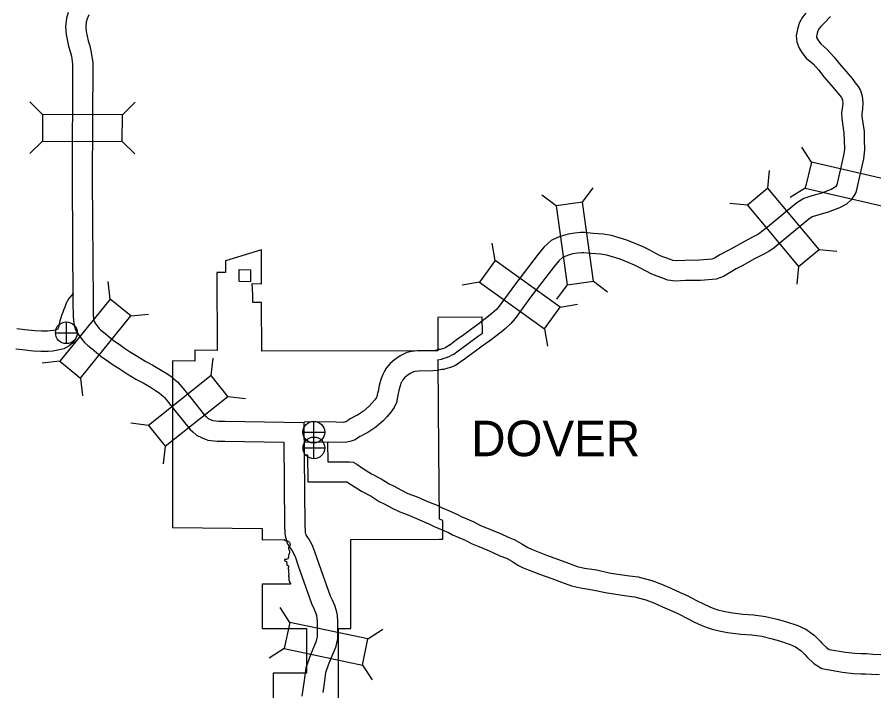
# Model space of a CAD drawing. Extents: x 1374139 to 1377472, y 1168351 to 1170484.
# Drawn here: x 1374519.6 to 1374646.9, y 1170238.9 to 1170339 of the extents above; entities that cross this region are included whole.
import ezdxf

# ---------------------------------------------------------------- set-up
doc = ezdxf.new("R2010")
doc.units = 0
doc.layers.add('Default', color=7, linetype='Continuous')

msp = doc.modelspace()

# ---------------------------------------------------------------- linework, layer by layer
at = {"layer": 'Default'}
for p, q in [((1374523.36, 1170324.58), (1374521.5, 1170326.45)), ((1374535.24, 1170324.53), (1374537.12, 1170326.4)), ((1374523.35, 1170320.62), (1374521.48, 1170318.76)), ((1374535.23, 1170320.57), (1374537.09, 1170318.7)), ((1374637.65, 1170317.48), (1374636.25, 1170319.72)), ((1374631.18, 1170313.62), (1374631.42, 1170316.25)), ((1374603.62, 1170311.55), (1374605.21, 1170313.66)), ((1374636.75, 1170313.62), (1374634.5, 1170312.23)), ((1374599.7, 1170311), (1374597.59, 1170312.59)), ((1374628.14, 1170311.08), (1374625.51, 1170311.32)), ((1374590.63, 1170302.85), (1374590.19, 1170305.45)), ((1374638.79, 1170304.5), (1374641.42, 1170304.26)), ((1374635.75, 1170301.96), (1374635.51, 1170299.33)), ((1374533.42, 1170297.12), (1374533.15, 1170299.74)), ((1374588.33, 1170299.63), (1374585.73, 1170299.19)), ((1374601.35, 1170299.24), (1374599.76, 1170297.13)), ((1374605.27, 1170299.79), (1374607.37, 1170298.2)), ((1374600.3, 1170295.95), (1374602.91, 1170296.39)), ((1374536.5, 1170294.62), (1374539.12, 1170294.9)), ((1374526.91, 1170290.5), (1374526.91, 1170293.75)), ((1374598, 1170292.73), (1374598.44, 1170290.13)), ((1374525.28, 1170292.13), (1374528.53, 1170292.13)), ((1374525.94, 1170287.89), (1374523.31, 1170287.62)), ((1374548.45, 1170285.75), (1374548.75, 1170288.37)), ((1374529.01, 1170285.4), (1374529.29, 1170282.77)), ((1374550.91, 1170282.65), (1374553.53, 1170282.35)), ((1374539.14, 1170278.36), (1374536.52, 1170278.67)), ((1374563.69, 1170275.72), (1374563.69, 1170278.97)), ((1374562.07, 1170277.35), (1374565.32, 1170277.35)), ((1374563.71, 1170273.39), (1374563.71, 1170276.64)), ((1374541.6, 1170275.26), (1374541.3, 1170272.64)), ((1374562.09, 1170275.01), (1374565.34, 1170275.01)), ((1374560.12, 1170249.07), (1374558.67, 1170251.29)), ((1374571.74, 1170246.62), (1374573.95, 1170248.06)), ((1374559.3, 1170245.2), (1374557.08, 1170243.76)), ((1374570.92, 1170242.74), (1374572.36, 1170240.53))]:
    msp.add_line(p, q, dxfattribs=at)
for points in [[(1374527.17, 1170339.73), (1374526.92, 1170338.89), (1374526.77, 1170337.57), (1374526.89, 1170336.43), (1374527.24, 1170334.73), (1374527.5, 1170333.94), (1374527.67, 1170333.24), (1374527.83, 1170332.06), (1374527.77, 1170314.82), (1374527.88, 1170296.68), (1374527.91, 1170294.6), (1374527.96, 1170293.93), (1374528.08, 1170293.27), (1374528.29, 1170292.57), (1374528.76, 1170291.78), (1374529.06, 1170291.35), (1374529.59, 1170290.69), (1374530.11, 1170290.23), (1374530.73, 1170289.73), (1374531.38, 1170289.19), (1374532.08, 1170288.61), (1374533.19, 1170287.84), (1374533.87, 1170287.34), (1374534.74, 1170286.8), (1374535.97, 1170286.04), (1374537.24, 1170285.25), (1374538.31, 1170284.69), (1374539.43, 1170284.02), (1374540.18, 1170283.56), (1374540.69, 1170283.2), (1374541.05, 1170282.92), (1374541.35, 1170282.66), (1374541.51, 1170282.49), (1374543.06, 1170280.56)], [(1374530.24, 1170339.39), (1374530.02, 1170338.79), (1374529.87, 1170338.29), (1374529.79, 1170337.55), (1374529.85, 1170336.89), (1374530.15, 1170335.51), (1374530.39, 1170334.76), (1374530.62, 1170333.79), (1374530.83, 1170332.26), (1374530.77, 1170314.83), (1374530.88, 1170296.71), (1374530.91, 1170294.74), (1374530.94, 1170294.31), (1374531, 1170293.97), (1374531.05, 1170293.79), (1374531.28, 1170293.41), (1374531.47, 1170293.15), (1374531.77, 1170292.76), (1374532.06, 1170292.51), (1374532.63, 1170292.05), (1374533.28, 1170291.51), (1374533.89, 1170291.01), (1374534.94, 1170290.28), (1374535.55, 1170289.82), (1374536.32, 1170289.35), (1374537.54, 1170288.59), (1374538.73, 1170287.86), (1374539.77, 1170287.31), (1374540.99, 1170286.59), (1374541.84, 1170286.06), (1374542.48, 1170285.61), (1374542.96, 1170285.24), (1374543.44, 1170284.82), (1374543.78, 1170284.45), (1374545.4, 1170282.45)], [(1374636.82, 1170339.63), (1374636.32, 1170339.02), (1374635.87, 1170338.21), (1374635.62, 1170337.43), (1374635.37, 1170336.28), (1374635.5, 1170335.3), (1374635.83, 1170334.42), (1374636.24, 1170333.76), (1374636.88, 1170332.95), (1374637.9, 1170332.09), (1374638.7, 1170331.19), (1374639.5, 1170330.18), (1374640.53, 1170328.98), (1374641.4, 1170327.98), (1374641.82, 1170327.43), (1374642.12, 1170327.07), (1374642.18, 1170326.95), (1374642.27, 1170326.67), (1374642.31, 1170326.3), (1374642.26, 1170325.69), (1374642.14, 1170324.86), (1374642.16, 1170323.97), (1374642.35, 1170322.88), (1374642.48, 1170321.8), (1374642.51, 1170320.75), (1374642.56, 1170319.42), (1374642.44, 1170318.49), (1374641.42, 1170314.11), (1374641.24, 1170313.82), (1374641.11, 1170313.69), (1374640.61, 1170313.42), (1374639.18, 1170312.89), (1374637.74, 1170312.45), (1374636.52, 1170312.1), (1374635.51, 1170311.45), (1374631.14, 1170307.81), (1374630.31, 1170307.15), (1374629.78, 1170306.78), (1374628.88, 1170306.31), (1374627.7, 1170305.68), (1374626.03, 1170304.76), (1374625.06, 1170304.25), (1374624.04, 1170303.69), (1374623.27, 1170303.21), (1374622.87, 1170303.07), (1374621, 1170302.9), (1374618.85, 1170302.86), (1374617.6, 1170302.81), (1374617.06, 1170302.88), (1374616.69, 1170303.02), (1374615.17, 1170303.57), (1374613.53, 1170304.43), (1374612.63, 1170304.9), (1374611.55, 1170305.36), (1374610.22, 1170305.88), (1374607.92, 1170306.57), (1374606.7, 1170306.78), (1374605.21, 1170306.89), (1374603.99, 1170307.02), (1374603.32, 1170307.02), (1374602.48, 1170306.91), (1374601.52, 1170306.78), (1374600.8, 1170306.56), (1374599.92, 1170306.28), (1374598.98, 1170305.84), (1374597.92, 1170304.9), (1374597.04, 1170303.81), (1374593.5, 1170299.22), (1374591.25, 1170296.08), (1374590.84, 1170295.58), (1374590.15, 1170294.98), (1374589.63, 1170294.52), (1374588.07, 1170293.35), (1374586.96, 1170292.54), (1374585.99, 1170291.84), (1374585.03, 1170291.16), (1374584.43, 1170290.68), (1374583.9, 1170290.3)], [(1374640.5, 1170339.14), (1374639.62, 1170338.2), (1374639.05, 1170337.62), (1374638.82, 1170337.33), (1374638.63, 1170337), (1374638.52, 1170336.65), (1374638.42, 1170336.16), (1374638.43, 1170336.02), (1374638.54, 1170335.74), (1374638.7, 1170335.49), (1374639.05, 1170335.04), (1374640, 1170334.24), (1374640.99, 1170333.13), (1374641.82, 1170332.09), (1374642.81, 1170330.93), (1374643.71, 1170329.89), (1374644.18, 1170329.29), (1374644.63, 1170328.73), (1374644.96, 1170328.12), (1374645.21, 1170327.29), (1374645.32, 1170326.36), (1374645.24, 1170325.35), (1374645.14, 1170324.67), (1374645.15, 1170324.26), (1374645.31, 1170323.33), (1374645.48, 1170322.03), (1374645.51, 1170320.84), (1374645.56, 1170319.29), (1374645.4, 1170317.96), (1374644.24, 1170312.98), (1374643.6, 1170311.91), (1374642.86, 1170311.23), (1374641.84, 1170310.68), (1374640.14, 1170310.05), (1374638.59, 1170309.58), (1374637.78, 1170309.34), (1374637.29, 1170309.03), (1374633.03, 1170305.48), (1374632.1, 1170304.74), (1374631.35, 1170304.22), (1374630.28, 1170303.65), (1374629.12, 1170303.04), (1374627.45, 1170302.12), (1374626.49, 1170301.62), (1374625.56, 1170301.1), (1374624.58, 1170300.49), (1374623.51, 1170300.11), (1374621.16, 1170299.91), (1374618.94, 1170299.87), (1374617.47, 1170299.8), (1374616.32, 1170299.95), (1374615.65, 1170300.2), (1374613.96, 1170300.81), (1374612.15, 1170301.77), (1374611.35, 1170302.18), (1374610.41, 1170302.58), (1374609.24, 1170303.04), (1374607.24, 1170303.64), (1374606.34, 1170303.79), (1374604.93, 1170303.9), (1374603.83, 1170304.02), (1374603.53, 1170304.02), (1374602.87, 1170303.94), (1374602.15, 1170303.83), (1374601.68, 1170303.7), (1374601.02, 1170303.48), (1374600.65, 1170303.31), (1374600.1, 1170302.82), (1374599.4, 1170301.95), (1374595.91, 1170297.43), (1374593.63, 1170294.24), (1374592.99, 1170293.48), (1374592.13, 1170292.73), (1374591.52, 1170292.19), (1374589.86, 1170290.94), (1374588.73, 1170290.11), (1374587.73, 1170289.39), (1374586.83, 1170288.76), (1374586.23, 1170288.28), (1374585.62, 1170287.85)], [(1374582.13, 1170289.46), (1374555.96, 1170289.37), (1374555.93, 1170296.62), (1374554.62, 1170296.64), (1374554.61, 1170297.71), (1374554.55, 1170299.44), (1374555.92, 1170299.42), (1374555.91, 1170300.99), (1374555.9, 1170304.45), (1374550.56, 1170302.81), (1374550.56, 1170301.06), (1374549.28, 1170301.08), (1374549.33, 1170289.49), (1374546.01, 1170289.55), (1374546.02, 1170287.9), (1374542.7, 1170287.96), (1374542.71, 1170274.75), (1374542.71, 1170263.19), (1374556, 1170263.02), (1374556, 1170261.37), (1374559.29, 1170261.38), (1374559.49, 1170261.26), (1374559.75, 1170261.21), (1374559.94, 1170261.1), (1374560.07, 1170260.93), (1374560.16, 1170260.76), (1374560.16, 1170260.57), (1374560.11, 1170260.46), (1374559.99, 1170260.33), (1374559.93, 1170260.23), (1374559.93, 1170260.03), (1374559.97, 1170259.9), (1374560.04, 1170259.8), (1374560.06, 1170259.65), (1374560.07, 1170259.44)], [(1374552.61, 1170301.52), (1374554.26, 1170301.5), (1374554.27, 1170299.69), (1374552.62, 1170299.72), (1374552.61, 1170301.52)], [(1374527.91, 1170297.99), (1374527.9, 1170297.98), (1374527.3, 1170297.21), (1374526.89, 1170296.51), (1374526.7, 1170295.95), (1374526.5, 1170295.46), (1374526.34, 1170295.04), (1374526.26, 1170294.83), (1374526.09, 1170294.36), (1374525.96, 1170293.89), (1374525.81, 1170293.19), (1374525.75, 1170292.92), (1374525.64, 1170292.69), (1374525.63, 1170292.66), (1374525.62, 1170292.66), (1374525.42, 1170292.55), (1374525.07, 1170292.46), (1374524.57, 1170292.39), (1374524.1, 1170292.35), (1374523.21, 1170292.35), (1374522.23, 1170292.4), (1374520.72, 1170292.58), (1374519.54, 1170292.7)], [(1374582.16, 1170287.81), (1374582.15, 1170288.1), (1374582.65, 1170288.22), (1374583.06, 1170288.33), (1374583.43, 1170288.45), (1374583.79, 1170288.61), (1374584.18, 1170288.8), (1374584.49, 1170288.96), (1374584.72, 1170289.11), (1374584.94, 1170289.27), (1374586.46, 1170290.4), (1374588.18, 1170291.67), (1374588.75, 1170292.08), (1374588.74, 1170294.46), (1374582.13, 1170294.4), (1374582.13, 1170289.46)], [(1374528.59, 1170291.94), (1374528.27, 1170291.2), (1374527.85, 1170290.61), (1374527.31, 1170290.17), (1374526.53, 1170289.73), (1374525.66, 1170289.52), (1374524.92, 1170289.41), (1374524.22, 1170289.34), (1374523.12, 1170289.35), (1374521.98, 1170289.41), (1374520.39, 1170289.59), (1374519.4, 1170289.7)], [(1374583.91, 1170290.32), (1374583.56, 1170290.08), (1374583.31, 1170289.91), (1374583.16, 1170289.84), (1374582.82, 1170289.75), (1374582.46, 1170289.65), (1374582.21, 1170289.63), (1374581.59, 1170289.46), (1374581.36, 1170289.45), (1374579.1, 1170289.42), (1374578.24, 1170289.32), (1374577.54, 1170289.17), (1374576.52, 1170288.71), (1374575.68, 1170288.11), (1374575.04, 1170287.55), (1374574.46, 1170286.86), (1374574.14, 1170286.3), (1374573.95, 1170285.94), (1374573.67, 1170285.18), (1374573.4, 1170284.27), (1374573.24, 1170283.44), (1374573.12, 1170282.89), (1374573.08, 1170282.67), (1374573.01, 1170282.51), (1374572.77, 1170282.17), (1374572.32, 1170281.64), (1374571.92, 1170281.22), (1374571.08, 1170280.48), (1374570.18, 1170279.9), (1374569.84, 1170279.72), (1374569.18, 1170279.38), (1374568.82, 1170279.15), (1374568.64, 1170279.01), (1374568.49, 1170278.91), (1374568.39, 1170278.87), (1374568.12, 1170278.81), (1374565.92, 1170278.87), (1374562.24, 1170278.83)], [(1374585.6, 1170287.84), (1374585.24, 1170287.59), (1374584.76, 1170287.27), (1374584.17, 1170287.01), (1374583.61, 1170286.86), (1374582.99, 1170286.68), (1374582.73, 1170286.66), (1374582.09, 1170286.5), (1374581.5, 1170286.45), (1374579.28, 1170286.42), (1374578.73, 1170286.36), (1374578.49, 1170286.31), (1374578.02, 1170286.09), (1374577.53, 1170285.74), (1374577.18, 1170285.45), (1374576.93, 1170285.14), (1374576.76, 1170284.84), (1374576.7, 1170284.72), (1374576.52, 1170284.24), (1374576.32, 1170283.56), (1374576.18, 1170282.83), (1374576.07, 1170282.31), (1374575.97, 1170281.77), (1374575.63, 1170281.03), (1374575.15, 1170280.34), (1374574.56, 1170279.64), (1374574.01, 1170279.06), (1374572.89, 1170278.08), (1374571.7, 1170277.32), (1374571.24, 1170277.07), (1374570.69, 1170276.78), (1374570.55, 1170276.69), (1374570.36, 1170276.55), (1374569.85, 1170276.22), (1374569.26, 1170275.99), (1374568.41, 1170275.8), (1374565.89, 1170275.87), (1374562.27, 1170275.83)], [(1374567.36, 1170234.97), (1374567.36, 1170248.18), (1374569.19, 1170248.18), (1374569.19, 1170254.79), (1374569.19, 1170261.4), (1374582.39, 1170261.44), (1374582.89, 1170261.44), (1374582.86, 1170264.21), (1374582.36, 1170264.44), (1374582.27, 1170274.62), (1374582.16, 1170287.81)], [(1374545.41, 1170282.44), (1374547.44, 1170279.88), (1374547.71, 1170279.67), (1374547.99, 1170279.4), (1374548.31, 1170279.25), (1374548.68, 1170279.1), (1374549.51, 1170279), (1374550.52, 1170278.99), (1374562.22, 1170278.8), (1374562.35, 1170263.53), (1374562.39, 1170262.61), (1374562.42, 1170262.38), (1374562.44, 1170262.31), (1374562.5, 1170262.08), (1374562.65, 1170261.83), (1374563.01, 1170261.33), (1374563.39, 1170260.68), (1374563.76, 1170259.76), (1374564.19, 1170258.48), (1374566.14, 1170253.01), (1374566.4, 1170252.42), (1374566.77, 1170251.65), (1374567.02, 1170250.83), (1374567.14, 1170250.1), (1374567.21, 1170249.27), (1374567.21, 1170247.92), (1374567.21, 1170246.66), (1374566.94, 1170245.36), (1374565.99, 1170243.14), (1374565.44, 1170241.61), (1374565.23, 1170240.04), (1374565.01, 1170238.66)], [(1374543.06, 1170280.57), (1374545.3, 1170277.74), (1374545.73, 1170277.4), (1374546.26, 1170276.9), (1374547.1, 1170276.5), (1374547.95, 1170276.16), (1374549.32, 1170276.01), (1374550.47, 1170275.99), (1374559.25, 1170275.85), (1374559.35, 1170263.47), (1374559.39, 1170262.35), (1374559.49, 1170261.68), (1374559.57, 1170261.45), (1374559.73, 1170260.81), (1374559.89, 1170260.6), (1374560.13, 1170260.19), (1374560.49, 1170259.7), (1374560.69, 1170259.35), (1374560.95, 1170258.72), (1374561.36, 1170257.5), (1374563.35, 1170251.89), (1374563.68, 1170251.17), (1374563.96, 1170250.56), (1374564.1, 1170250.13), (1374564.16, 1170249.73), (1374564.21, 1170249.15), (1374564.21, 1170247.92), (1374564.21, 1170246.97), (1374564.06, 1170246.27), (1374563.2, 1170244.24), (1374562.5, 1170242.32), (1374562.26, 1170240.47), (1374562.04, 1170239.1), (1374561.9, 1170238.12)], [(1374565.73, 1170275.83), (1374565.77, 1170272.96), (1374568.45, 1170272.96), (1374569, 1170272.94), (1374569.55, 1170272.87), (1374570.07, 1170272.59), (1374570.93, 1170272.01), (1374572.27, 1170271.17), (1374573.69, 1170270.44), (1374574.9, 1170269.69), (1374575.64, 1170269.31), (1374576.61, 1170268.79), (1374577.67, 1170268.26), (1374578.38, 1170268), (1374579.08, 1170267.74), (1374580.15, 1170267.26), (1374581.23, 1170266.8), (1374582.02, 1170266.48), (1374582.79, 1170266.09), (1374583.97, 1170265.62), (1374585.06, 1170265.12), (1374585.62, 1170264.8), (1374586.42, 1170264.47), (1374587.48, 1170264.01), (1374588.49, 1170263.49), (1374589.35, 1170263.13), (1374590.53, 1170262.65), (1374591.45, 1170262.28), (1374592.56, 1170261.73), (1374593.59, 1170261.33), (1374594.63, 1170260.76), (1374595.5, 1170260.23), (1374596.06, 1170259.95), (1374598.29, 1170259.06), (1374600.08, 1170258.44), (1374601.55, 1170257.87), (1374602.83, 1170257.41), (1374603.92, 1170257.16), (1374605.69, 1170256.88), (1374607.83, 1170256.4), (1374610.6, 1170256.01), (1374611.92, 1170255.86), (1374613.96, 1170255.29), (1374615.38, 1170254.74), (1374616.74, 1170254.15), (1374618.13, 1170253.52), (1374619.19, 1170253.06), (1374620.57, 1170252.34), (1374621.6, 1170251.84), (1374622.57, 1170251.38), (1374623.17, 1170251.13), (1374623.74, 1170250.95), (1374624.58, 1170250.74), (1374625.63, 1170250.54), (1374627.46, 1170250.32), (1374629.07, 1170250.2), (1374630.85, 1170249.98), (1374632.58, 1170249.55), (1374633.8, 1170249.23), (1374635.63, 1170248.61), (1374636.83, 1170248.05), (1374638.06, 1170247.17), (1374638.95, 1170246.31), (1374639.19, 1170246.01), (1374639.88, 1170245.34), (1374640.31, 1170245.07), (1374642.7, 1170244.65), (1374644.12, 1170244.5), (1374645.09, 1170244.46), (1374645.84, 1170244.45), (1374646.79, 1170244.37), (1374647.97, 1170244.32)], [(1374562.33, 1170273.96), (1374562.75, 1170273.96), (1374562.8, 1170269.95), (1374568.39, 1170269.96), (1374568.61, 1170269.95), (1374569.3, 1170269.5), (1374570.79, 1170268.56), (1374572.21, 1170267.83), (1374573.43, 1170267.07), (1374574.26, 1170266.65), (1374575.23, 1170266.13), (1374576.48, 1170265.5), (1374577.34, 1170265.19), (1374577.93, 1170264.96), (1374578.95, 1170264.5), (1374580.08, 1170264.03), (1374580.77, 1170263.75), (1374581.56, 1170263.35), (1374582.79, 1170262.86), (1374583.7, 1170262.44), (1374584.3, 1170262.1), (1374585.23, 1170261.71), (1374586.19, 1170261.29), (1374587.23, 1170260.76), (1374588.21, 1170260.36), (1374589.4, 1170259.87), (1374590.22, 1170259.54), (1374591.35, 1170258.99), (1374592.32, 1170258.61), (1374593.13, 1170258.17), (1374594.03, 1170257.61), (1374594.83, 1170257.21), (1374597.24, 1170256.25), (1374599.05, 1170255.62), (1374600.51, 1170255.06), (1374601.98, 1170254.53), (1374603.34, 1170254.21), (1374605.13, 1170253.93), (1374607.29, 1170253.45), (1374610.22, 1170253.03), (1374611.34, 1170252.9), (1374613.02, 1170252.44), (1374614.23, 1170251.97), (1374615.52, 1170251.41), (1374616.91, 1170250.78), (1374617.9, 1170250.35), (1374619.22, 1170249.66), (1374620.3, 1170249.13), (1374621.36, 1170248.63), (1374622.15, 1170248.31), (1374622.92, 1170248.06), (1374623.95, 1170247.81), (1374625.18, 1170247.58), (1374627.17, 1170247.33), (1374628.78, 1170247.22), (1374630.3, 1170247.03), (1374631.84, 1170246.64), (1374632.93, 1170246.36), (1374634.51, 1170245.82), (1374635.31, 1170245.45), (1374636.13, 1170244.86), (1374636.73, 1170244.28), (1374636.97, 1170243.98), (1374638.03, 1170242.96), (1374639.21, 1170242.22), (1374642.28, 1170241.67), (1374643.9, 1170241.51), (1374645, 1170241.46), (1374645.69, 1170241.45), (1374646.61, 1170241.38), (1374647.78, 1170241.33)], [(1374560.07, 1170259.44), (1374559.99, 1170259.17), (1374559.94, 1170258.98), (1374559.92, 1170258.76), (1374559.89, 1170258.63), (1374559.81, 1170258.54), (1374559.68, 1170258.48), (1374559.56, 1170258.45), (1374559.45, 1170258.45), (1374559.36, 1170258.41), (1374559.35, 1170258.33), (1374559.38, 1170258.25), (1374559.49, 1170258.19), (1374559.61, 1170258.11), (1374559.67, 1170257.95), (1374559.65, 1170257.89), (1374559.67, 1170257.72), (1374559.7, 1170257.59), (1374559.77, 1170257.58), (1374559.84, 1170257.52), (1374559.92, 1170257.4), (1374559.93, 1170257.29), (1374559.88, 1170257.16), (1374559.89, 1170257.04), (1374559.94, 1170256.9), (1374559.95, 1170256.8), (1374559.94, 1170256.66), (1374559.95, 1170256.52), (1374559.99, 1170256.32), (1374559.99, 1170256.18), (1374559.95, 1170256.04), (1374559.95, 1170255.94), (1374559.98, 1170255.82), (1374559.99, 1170255.73), (1374559.99, 1170255.63), (1374559.98, 1170255.55), (1374559.99, 1170255.41), (1374560.02, 1170255.27), (1374560.06, 1170255.13), (1374560.09, 1170255.07), (1374560.14, 1170254.99), (1374560.21, 1170254.85), (1374560.21, 1170254.77)], [(1374560.21, 1170254.77), (1374556.02, 1170254.76), (1374556.04, 1170248.15), (1374562.62, 1170248.16), (1374562.63, 1170241.55), (1374557.63, 1170241.54), (1374557.64, 1170234.93), (1374555.97, 1170234.92), (1374555.9, 1170222.81), (1374558.5, 1170222.8), (1374558.5, 1170216.2), (1374555.9, 1170216.21), (1374549.37, 1170216.28), (1374549.35, 1170209.63), (1374549.39, 1170196.4), (1374542.79, 1170196.46), (1374542.79, 1170183.22)]]:
    msp.add_lwpolyline(points, dxfattribs=at)
for points in [[(1374523.35, 1170320.62), (1374535.23, 1170320.57), (1374535.24, 1170324.53), (1374523.36, 1170324.58)], [(1374649.22, 1170314.78), (1374637.65, 1170317.48), (1374636.75, 1170313.62), (1374648.31, 1170310.92)], [(1374628.14, 1170311.08), (1374635.75, 1170301.96), (1374638.79, 1170304.5), (1374631.18, 1170313.62)], [(1374599.7, 1170311), (1374601.35, 1170299.24), (1374605.27, 1170299.79), (1374603.62, 1170311.55)], [(1374588.33, 1170299.63), (1374598, 1170292.73), (1374600.3, 1170295.95), (1374590.63, 1170302.85)], [(1374529.01, 1170285.4), (1374536.5, 1170294.62), (1374533.42, 1170297.12), (1374525.94, 1170287.89)], [(1374548.45, 1170285.75), (1374539.14, 1170278.36), (1374541.6, 1170275.26), (1374550.91, 1170282.65)], [(1374571.74, 1170246.62), (1374560.12, 1170249.07), (1374559.3, 1170245.2), (1374570.92, 1170242.74)]]:
    msp.add_lwpolyline(points, close=True, dxfattribs=at)
for centre in [(1374526.91, 1170292.13), (1374563.69, 1170277.35), (1374563.71, 1170275.01)]:
    msp.add_circle(centre, 1.62, dxfattribs=at)

# ---------------------------------------------------------------- texts
msp.add_text('DOVER', height=5.28, dxfattribs=at).set_placement((1374587.09, 1170273.78))

doc.saveas('drawing.dxf')
